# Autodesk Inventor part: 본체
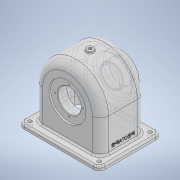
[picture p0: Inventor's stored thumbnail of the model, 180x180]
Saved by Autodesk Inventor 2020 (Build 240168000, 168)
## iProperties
Created: 2022-09
Part Number: 본체
Material: 일반
Document SubType Name: Modeling
Designer: USER
Density: 1 g/cm^3
Appearance: 기본값
Author: USER
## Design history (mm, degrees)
sketch "스케치2"
  geometry: L1 (-57, -64)-(-57, 0); L2 (57, 0)-(57, -64); L3 (57, -64)-(-57, -64); A1 r 57 centre (0, 0) between (57, 0) and (-57, 0); 2 further points
  constraints: 6 end point, 2 point on circle, 1 centre point, 1 coincident, 1 horizontal alignment, 1 midpoint, 1 perpendicular, 1 tangent, 1 vertical, 1 vertical alignment
  dimensions: "d0" = 114 diameter of A1; "d3" = 64 distance from line of point (0, 0) L3
extrude "돌출1" new body sketch "스케치2" distance "d4" = 78; taper "d5" = 0 deg
sketch "스케치3"
  geometry: C1 r 31 at (0, 0); 1 further point
  constraints: 1 centre point, 1 coincident
  dimensions: "d6" = 62 diameter of C1
extrude "돌출2" join sketch "스케치3" distance "d7" = 15; taper "d8" = 0 deg
node "작업 평면1"
sketch "스케치5"
  geometry: L1 (-13, 15)-(127, 15); L2 (127, 15)-(127, -93); L3 (127, -93)-(-13, -93); L4 (-13, -93)-(-13, 15); L5 (0, -78)-(0, 0) reference; L6 (0, 0)-(114, 0) reference; L7 (114, 0)-(114, -78) reference; L8 (114, -78)-(0, -78) reference; 5 further points
  constraints: 8 end point, 4 midpoint, 2 parallel, 1 horizontal, 1 horizontal alignment, 1 perpendicular, 1 vertical alignment
  dimensions: "d12" = 140 distance of L1.start L1.end; "d13" = 108 distance of L1.end L2.end
extrude "돌출4" join sketch "스케치5" distance "d14" = 7; taper "d15" = 0 deg
sketch "스케치4"
  geometry: L1 (-57, -57)-(-57, 0) reference; L2 (57, 0)-(57, -57) reference; L3 (-52, 0)-(-52, -85.984); L4 (52, -79.891)-(52, 0); L5 (-52, -85.984)-(52, -79.891); L6 (57, -57)-(70, -57) reference; L7 (70, -57)-(70, -64) reference; L8 (70, -64)-(-70, -64) reference; L9 (-70, -64)-(-70, -57) reference; L10 (-70, -57)-(-57, -57) reference; A1 r 57 centre (0, 0) between (57, 0) and (-57, 0) reference; A2 r 52 centre (0, 0) between (52, 0) and (-52, 0); 1 further point
  constraints: 7 end point, 2 point on circle, 1 centre point, 1 horizontal alignment, 1 vertical, 1 other
  dimensions: "d9" = 5 radial gap between concentric circles of A1 A2
extrude "돌출3" cut sketch "스케치4" stored distance "d10" = 68; taper "d11" = 0 deg
sketch "스케치6"
  geometry: L1 (0, -13.706)-(0, -110.185); L2 (36.083, -5)-(28, -19); L3 (28, -19)-(20, -19); L4 (20, -19)-(20, -5); L5 (20, -5)-(36.083, -5); L6 (57, -78)-(31, -78) reference; L7 (-31, -93)-(-31, -78) reference; L8 (31, -93)-(-31, -93) reference; L9 (31, -78)-(31, -93) reference; L10 (-31, -78)-(-57, -78) reference; L11 (-57, -78)-(-57, -93) reference; L12 (-57, -93)-(-64, -93) reference; L13 (-64, -93)-(-64, -73) reference; L14 (-64, -73)-(52, -73) reference; L15 (52, -73)-(52, -5) reference; L16 (52, -5)-(-64, -5) reference; L17 (-64, -5)-(-64, 15) reference; L18 (-64, 15)-(-57, 15) reference; L19 (-57, 15)-(-57, 0) reference; L20 (-57, 0)-(57, 0) reference; L21 (57, 0)-(57, -78) reference; 1 further point
  constraints: 10 end point, 2 perpendicular, 1 collinear, 1 horizontal, 1 vertical, 1 vertical alignment
  dimensions: "d16" = 14 distance between parallel lines of L3 L5; "d17" = 56 diameter of L2.end L1; "d18" = 30 deg angle of L4 L2; "d19" = 40 diameter of L4 L1
revolve "회전1" sketch "스케치6" stored, may be unused: angle "d20" = 90 deg
sketch "스케치7"
  geometry: L1 (0, 0)-(0, -128.844); L2 (0, 0)-(-57, 0) reference; L3 (0, 0)-(32, 0); L4 (32, 0)-(32, -3); L5 (32, -3)-(0, -3); L6 (0, -3)-(0, 0); L7 (0, 0)-(0, -78) reference; L8 (20, -3)-(0, -3); L9 (0, -3)-(0, -19); L10 (0, -19)-(20, -19); L11 (20, -19)-(20, -3); L12 (17.5, -73)-(0, -73); L13 (0, -73)-(0, -77); L14 (17.5, -77)-(17.5, -73); L15 (20, -77)-(17.5, -77); L16 (0, -77)-(0, -93); L17 (0, -93)-(20, -93); L18 (20, -93)-(20, -77); L19 (57, -78)-(31, -78) reference; L20 (-31, -93)-(-31, -78) reference; L21 (31, -93)-(-31, -93) reference; L22 (31, -78)-(31, -93) reference; L23 (-31, -78)-(-57, -78) reference; L24 (-57, -78)-(-57, -93) reference; L25 (-57, -93)-(-64, -93) reference; L26 (-64, -93)-(-64, -73) reference; L27 (-64, -73)-(52, -73) reference; L28 (52, -73)-(52, -5) reference; L29 (52, -5)-(36.083, -5) reference; L30 (36.083, -5)-(28, -19) reference; L31 (28, -19)-(20, -19) reference; L32 (20, -19)-(20, -5) reference; L33 (20, -5)-(-20, -5) reference; L34 (-20, -5)-(-20, -19) reference; L35 (-20, -19)-(-28, -19) reference; L36 (-28, -19)-(-36.083, -5) reference; L37 (-36.083, -5)-(-64, -5) reference; L38 (-64, -5)-(-64, 15) reference; L39 (-64, 15)-(-57, 15) reference; L40 (-57, 15)-(-57, 0) reference; L41 (-57, 0)-(57, 0) reference; L42 (57, 0)-(57, -78) reference; L43 (20, -77)-(17.5, -77); 4 further points
  constraints: 34 end point, 8 parallel, 4 collinear, 4 horizontal, 4 perpendicular, 4 point on line, 1 coincident, 1 vertical
  dimensions: "d21" = 40 diameter of L18 L1; "d22" = 35 diameter of L14 L1; "d23" = 16 distance of L17.end L15.start; "d24" = 16 distance of L10.end L8.start; "d25" = 40 diameter of L11 L1; "d26" = 64 diameter of L4 L1
revolve "회전2" sketch "스케치7" stored, may be unused: angle "d27" = 90 deg
node "작업 평면2"
sketch "스케치8"
  geometry: L1 (13, -15)-(13, -93) reference; C1 r 6 at (70, -54); 2 further points
  constraints: 1 centre point, 1 horizontal alignment, 1 midpoint, 1 vertical alignment
  dimensions: "d29" = 12 diameter of C1
extrude "돌출5" join sketch "스케치8" stored distance "d30" = 7; taper "d31" = 0 deg
sketch "스케치9"
  geometry: C1 r 6 at (0, 0) reference; 2 further points
  constraints: 1 coincident
hole "구멍1" sketch "스케치9" at (0, 0) diameter "d32" = 5.1881; stored, may be unused: countersink angle "d36" = 90 deg, drill point angle "d38" = 118 deg; dims "d33" = 12, "d34" = 4, "d35" = 2, "d37" = 16
sketch "스케치10"
  geometry: A1 r 24 centre (0, 0) between (0, 24) and (-24, 0); 3 further points
  constraints: 4 point on circle, 2 horizontal alignment, 2 vertical alignment, 1 centre point, 1 coincident
  dimensions: "d39" = 48 diameter of A1
sketch "스케치11"
  geometry: A1 r 24 centre (0, 0) between (0, 24) and (-24, 0); 3 further points
  constraints: 4 point on circle, 2 horizontal alignment, 2 vertical alignment, 1 centre point, 1 coincident
  dimensions: "d40" = 48 diameter of A1
hole "구멍2" sketch "스케치10" diameter "d41" = 2.459; stored, may be unused: countersink angle "d45" = 90 deg, drill point angle "d47" = 118 deg; dims "d42" = 7, "d43" = 4, "d44" = 2, "d46" = 9
hole "구멍3" sketch "스케치11" diameter "d48" = 2.459; stored, may be unused: countersink angle "d52" = 90 deg, drill point angle "d54" = 118 deg; dims "d49" = 7, "d50" = 4, "d51" = 2, "d53" = 9
fillet "모깎기1" dims "d55" = 10, "d56" = 14
sketch "스케치12"
  geometry: A1 r 10 centre (-3, -5) between (-13, -5) and (-3, -15) reference; A2 r 10 centre (-3, 83) between (-3, 93) and (-13, 83) reference; A3 r 10 centre (117, 83) between (127, 83) and (117, 93) reference; A4 r 10 centre (117, -5) between (117, -15) and (127, -5) reference; 1 further point
hole "구멍4" sketch "스케치12" at (-3, -5), (117, -5), (117, 83), (-3, 83) diameter "d57" = 6.6; stored, may be unused: countersink angle "d61" = 90 deg, drill point angle "d63" = 118 deg; dims "d58" = 7, "d59" = 4, "d60" = 2, "d62" = 9
sketch "스케치13"
  geometry: L1 (69, -7)-(-19, -7) reference; L2 (-14, 57)-(-14, 0) reference; 1 further point
  constraints: 1 other
  dimensions: "d64" = 17 distance from line of point (25, 10) L1; "d65" = 39 distance from line of L2 point (25, 10)
feature "엠보싱1" sketch "스케치13" dims "d66" = 0.5, "d67" = 0
fillet "모깎기2" dims "d68" = 1
fillet "모깎기3" dims "d69" = 0.6
chamfer "모따기1" distance "d70" = 1; stored, may be unused: second distance "d71" = 2, angle "d72" = 45 deg
fillet "모깎기4" dims "d73" = 9
fillet "모깎기5" dims "d74" = 3
node "솔리드1"
node "절단 모서리 투영1"
node "절단 모서리 투영2"
node "절단 모서리 투영3"
node "절단 모서리 투영4"
feature "A9D066F2-1C7D-4E18-AEED-F7BC21143FA4" dims "d57" = 6.6, "d58" = 7, "d59" = 4, "d60" = 2, "d61" = 90 deg, "d62" = 9, "d63" = 118 deg
other parameters: "d28" = -124
